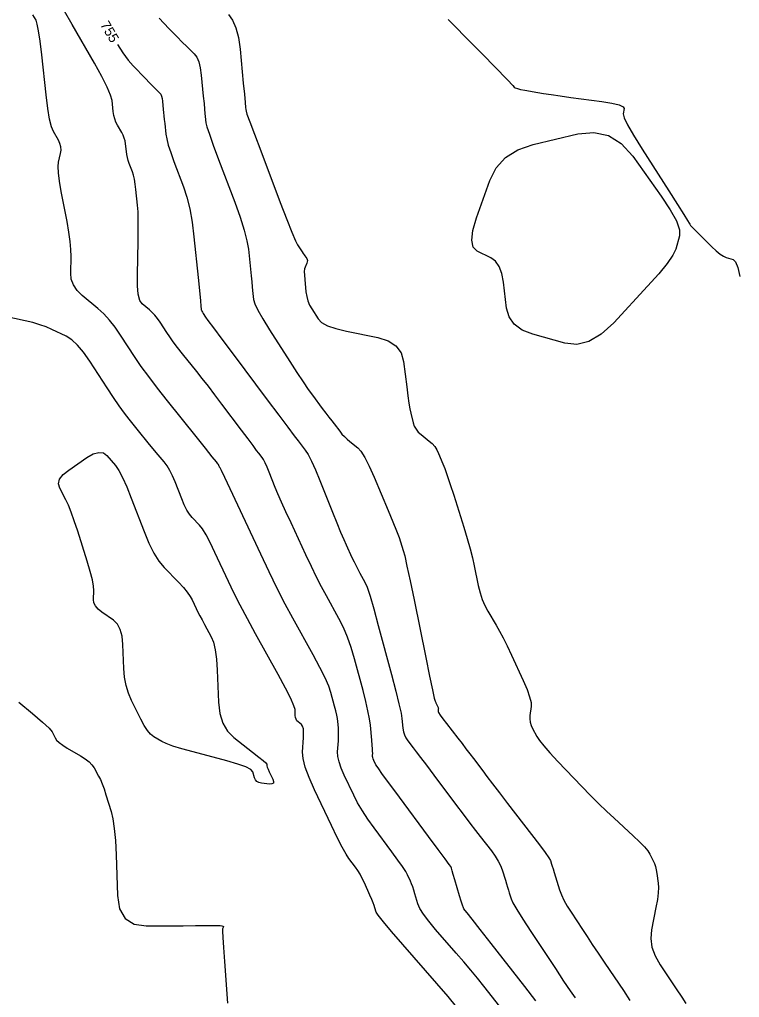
# Model space of a CAD drawing. Extents: x 2082232 to 2083549, y 592624 to 593832.
# Drawn here: x 2082855.5 to 2082906.4, y 592813 to 592882.1 of the extents above; entities that cross this region are included whole.
import ezdxf

# ---------------------------------------------------------------- set-up
doc = ezdxf.new("R2010")
doc.units = 0
doc.layers.add('DT_X_Contour_Major', color=7, linetype='Continuous')
doc.layers.add('DT_X_Contour_Minor', color=7, linetype='Continuous')

msp = doc.modelspace()

# ---------------------------------------------------------------- linework, layer by layer
at = {"layer": 'DT_X_Contour_Major'}
msp.add_lwpolyline([(2082862.437, 592880.32), (2082862.826, 592879.726), (2082863.203, 592879.215), (2082863.545, 592878.821), (2082864.412, 592877.926), (2082864.706, 592877.623), (2082864.939, 592877.384), (2082865.11, 592877.21), (2082865.219, 592877.101), (2082865.427, 592876.896), (2082865.498, 592876.802), (2082865.554, 592876.673), (2082865.596, 592876.511), (2082865.624, 592876.314), (2082865.679, 592875.742), (2082865.7, 592875.519), (2082865.724, 592875.278), (2082865.75, 592875.02), (2082865.779, 592874.744), (2082865.859, 592873.984), (2082865.917, 592873.65), (2082866.032, 592873.218), (2082866.203, 592872.688), (2082866.431, 592872.061), (2082867.114, 592870.256), (2082867.352, 592869.529), (2082867.552, 592868.702), (2082867.716, 592867.774), (2082867.843, 592866.746), (2082868.133, 592863.869), (2082868.297, 592862.237), (2082868.339, 592861.815), (2082868.355, 592861.656), (2082868.363, 592861.582), (2082868.373, 592861.545), (2082868.399, 592861.49), (2082868.44, 592861.417), (2082868.497, 592861.327), (2082868.667, 592861.061), (2082868.837, 592860.822), (2082869.217, 592860.307), (2082869.808, 592859.514), (2082870.609, 592858.444), (2082873.028, 592855.222), (2082873.845, 592854.135), (2082874.481, 592853.289), (2082874.937, 592852.684), (2082875.213, 592852.32), (2082875.708, 592851.672), (2082875.913, 592851.355), (2082876.153, 592850.891), (2082876.431, 592850.278), (2082876.745, 592849.519), (2082877.631, 592847.296), (2082877.942, 592846.525), (2082878.207, 592845.881), (2082878.428, 592845.362), (2082878.604, 592844.97), (2082879.013, 592844.092), (2082879.163, 592843.775), (2082879.308, 592843.482), (2082879.446, 592843.213), (2082879.578, 592842.967), (2082879.921, 592842.345), (2082880.077, 592841.978), (2082880.288, 592841.345), (2082880.554, 592840.445), (2082880.875, 592839.279), (2082881.803, 592835.814), (2082882.11, 592834.645), (2082882.336, 592833.737), (2082882.482, 592833.091), (2082882.546, 592832.705), (2082882.609, 592832.024), (2082882.648, 592831.777), (2082882.719, 592831.546), (2082882.82, 592831.332), (2082882.953, 592831.134), (2082883.349, 592830.627), (2082883.551, 592830.364), (2082883.86, 592829.958), (2082884.275, 592829.407), (2082884.798, 592828.712), (2082886.333, 592826.665), (2082886.874, 592825.946), (2082887.345, 592825.323), (2082887.746, 592824.797), (2082888.077, 592824.366), (2082888.866, 592823.348), (2082889.136, 592822.979), (2082889.353, 592822.636), (2082889.517, 592822.319), (2082889.628, 592822.027), (2082889.853, 592821.285), (2082889.934, 592821.021), (2082890.006, 592820.785), (2082890.07, 592820.577), (2082890.125, 592820.398), (2082890.263, 592819.957), (2082890.389, 592819.69), (2082890.664, 592819.218), (2082891.088, 592818.542), (2082891.661, 592817.661), (2082893.388, 592815.04), (2082893.974, 592814.155), (2082894.438, 592813.466), (2082894.779, 592812.972)], dxfattribs=at)
at = {"layer": 'DT_X_Contour_Minor'}
for points in [[(2082889.453, 592812.364), (2082888.324, 592813.804), (2082887.885, 592814.355), (2082887.415, 592814.928), (2082886.914, 592815.522), (2082886.383, 592816.138), (2082884.925, 592817.811), (2082884.437, 592818.393), (2082884.066, 592818.887), (2082883.811, 592819.291), (2082883.674, 592819.606), (2082883.463, 592820.327), (2082883.384, 592820.585), (2082883.305, 592820.819), (2082883.227, 592821.028), (2082883.149, 592821.213), (2082882.941, 592821.674), (2082882.814, 592821.905), (2082882.588, 592822.25), (2082882.264, 592822.711), (2082881.841, 592823.287), (2082880.583, 592824.977), (2082880.138, 592825.598), (2082879.749, 592826.192), (2082879.415, 592826.759), (2082879.137, 592827.301), (2082878.468, 592828.709), (2082878.251, 592829.207), (2082878.101, 592829.646), (2082878.018, 592830.026), (2082878.002, 592830.345), (2082878.05, 592831.119), (2082878.064, 592831.394), (2082878.069, 592831.64), (2082878.066, 592831.857), (2082878.054, 592832.045), (2082878.011, 592832.506), (2082877.985, 592832.703), (2082877.938, 592832.948), (2082877.872, 592833.24), (2082877.784, 592833.579), (2082877.525, 592834.547), (2082877.373, 592834.986), (2082877.112, 592835.576), (2082876.742, 592836.316), (2082876.263, 592837.208), (2082874.84, 592839.787), (2082874.297, 592840.795), (2082873.736, 592841.887), (2082873.157, 592843.062), (2082872.56, 592844.321), (2082870.943, 592847.787), (2082870.411, 592848.926), (2082870.028, 592849.743), (2082869.794, 592850.237), (2082869.708, 592850.41), (2082869.678, 592850.44), (2082869.667, 592850.454), (2082869.657, 592850.471), (2082869.646, 592850.491), (2082869.636, 592850.516), (2082869.61, 592850.585), (2082869.6, 592850.61), (2082869.589, 592850.631), (2082869.578, 592850.65), (2082869.566, 592850.666), (2082869.533, 592850.704), (2082869.428, 592850.834), (2082869.136, 592851.198), (2082868.658, 592851.794), (2082867.994, 592852.622), (2082865.974, 592855.143), (2082865.263, 592856.044), (2082864.645, 592856.857), (2082864.121, 592857.581), (2082863.689, 592858.218), (2082862.663, 592859.797), (2082862.275, 592860.359), (2082861.878, 592860.859), (2082861.473, 592861.297), (2082861.06, 592861.673), (2082859.948, 592862.595), (2082859.585, 592862.953), (2082859.328, 592863.335), (2082859.178, 592863.742), (2082859.135, 592864.172), (2082859.162, 592865.352), (2082859.152, 592865.839), (2082859.101, 592866.413), (2082859.009, 592867.075), (2082858.876, 592867.825), (2082858.468, 592869.941), (2082858.342, 592870.665), (2082858.267, 592871.25), (2082858.244, 592871.695), (2082858.274, 592872), (2082858.423, 592872.63), (2082858.455, 592872.865), (2082858.439, 592873.098), (2082858.376, 592873.329), (2082858.265, 592873.559), (2082857.907, 592874.169), (2082857.774, 592874.503), (2082857.646, 592875.045), (2082857.522, 592875.798), (2082857.402, 592876.759), (2082857.089, 592879.603), (2082856.975, 592880.555), (2082856.869, 592881.277), (2082856.772, 592881.769), (2082856.682, 592882.032), (2082856.454, 592882.427)], [(2082892.017, 592812.751), (2082891.234, 592813.783), (2082888.859, 592816.811), (2082888.076, 592817.809), (2082887.507, 592818.533), (2082887.154, 592818.981), (2082887.015, 592819.155), (2082886.93, 592819.252), (2082886.887, 592819.337), (2082886.821, 592819.519), (2082886.731, 592819.798), (2082886.618, 592820.175), (2082886.286, 592821.309), (2082886.176, 592821.684), (2082886.095, 592821.957), (2082886.042, 592822.129), (2082886.019, 592822.199), (2082885.996, 592822.251), (2082885.891, 592822.398), (2082885.596, 592822.8), (2082885.109, 592823.457), (2082884.43, 592824.368), (2082882.366, 592827.139), (2082881.682, 592828.062), (2082881.178, 592828.754), (2082880.854, 592829.215), (2082880.71, 592829.445), (2082880.566, 592829.748), (2082880.519, 592829.856), (2082880.487, 592829.95), (2082880.469, 592830.032), (2082880.465, 592830.101), (2082880.476, 592830.268), (2082880.475, 592830.372), (2082880.463, 592830.559), (2082880.442, 592830.83), (2082880.41, 592831.185), (2082880.312, 592832.242), (2082880.252, 592832.692), (2082880.146, 592833.252), (2082879.993, 592833.92), (2082879.794, 592834.697), (2082879.2, 592836.913), (2082878.964, 592837.716), (2082878.7, 592838.46), (2082878.41, 592839.147), (2082878.092, 592839.776), (2082877.209, 592841.377), (2082876.869, 592842.008), (2082876.514, 592842.701), (2082876.143, 592843.455), (2082875.756, 592844.27), (2082874.704, 592846.528), (2082874.338, 592847.319), (2082874.031, 592847.999), (2082873.782, 592848.569), (2082873.592, 592849.028), (2082873.163, 592850.105), (2082873.01, 592850.473), (2082872.876, 592850.769), (2082872.759, 592850.994), (2082872.661, 592851.148), (2082872.421, 592851.462), (2082872.277, 592851.651), (2082872.027, 592851.983), (2082871.67, 592852.457), (2082871.206, 592853.075), (2082869.827, 592854.913), (2082869.327, 592855.574), (2082868.863, 592856.181), (2082868.434, 592856.733), (2082868.04, 592857.229), (2082867.038, 592858.48), (2082866.686, 592858.925), (2082866.384, 592859.321), (2082866.132, 592859.669), (2082865.929, 592859.968), (2082865.453, 592860.701), (2082865.272, 592860.961), (2082865.088, 592861.193), (2082864.9, 592861.396), (2082864.709, 592861.571), (2082864.193, 592861.999), (2082864.026, 592862.249), (2082863.913, 592862.677), (2082863.853, 592863.284), (2082863.846, 592864.069), (2082863.9, 592866.402), (2082863.913, 592867.219), (2082863.91, 592867.92), (2082863.891, 592868.506), (2082863.858, 592868.975), (2082863.747, 592870.072), (2082863.701, 592870.46), (2082863.644, 592870.799), (2082863.576, 592871.09), (2082863.498, 592871.334), (2082863.277, 592871.919), (2082863.202, 592872.136), (2082863.142, 592872.35), (2082863.097, 592872.559), (2082863.068, 592872.764), (2082863.011, 592873.306), (2082862.978, 592873.509), (2082862.922, 592873.709), (2082862.842, 592873.907), (2082862.739, 592874.104), (2082862.432, 592874.625), (2082862.328, 592874.832), (2082862.244, 592875.063), (2082862.181, 592875.317), (2082862.139, 592875.595), (2082862.053, 592876.368), (2082861.951, 592876.749), (2082861.71, 592877.315), (2082861.328, 592878.065), (2082860.806, 592878.998), (2082859.228, 592881.733), (2082858.692, 592882.667)], [(2082870.28, 592882.433), (2082870.577, 592882.039), (2082870.814, 592881.5), (2082870.99, 592880.818), (2082871.106, 592879.993), (2082871.334, 592877.599), (2082871.409, 592876.808), (2082871.465, 592876.232), (2082871.499, 592875.869), (2082871.514, 592875.72), (2082871.526, 592875.609), (2082871.594, 592875.402), (2082871.79, 592874.865), (2082872.114, 592873.998), (2082872.566, 592872.8), (2082873.942, 592869.166), (2082874.405, 592867.957), (2082874.762, 592867.054), (2082875.013, 592866.458), (2082875.158, 592866.169), (2082875.404, 592865.806), (2082875.49, 592865.679), (2082875.566, 592865.568), (2082875.631, 592865.473), (2082875.685, 592865.396), (2082875.815, 592865.212), (2082875.851, 592865.138), (2082875.864, 592865.057), (2082875.854, 592864.968), (2082875.819, 592864.87), (2082875.695, 592864.6), (2082875.659, 592864.469), (2082875.643, 592864.28), (2082875.647, 592864.034), (2082875.671, 592863.729), (2082875.761, 592862.839), (2082875.812, 592862.514), (2082875.896, 592862.206), (2082876.015, 592861.916), (2082876.167, 592861.643), (2082876.619, 592860.939), (2082876.871, 592860.687), (2082877.289, 592860.459), (2082877.872, 592860.255), (2082878.62, 592860.075), (2082880.836, 592859.627), (2082881.574, 592859.396), (2082882.124, 592859.037), (2082882.488, 592858.55), (2082882.664, 592857.937), (2082882.884, 592856.13), (2082882.964, 592855.506), (2082883.039, 592854.989), (2082883.108, 592854.578), (2082883.173, 592854.274), (2082883.338, 592853.606), (2082883.419, 592853.365), (2082883.54, 592853.145), (2082883.699, 592852.944), (2082883.897, 592852.763), (2082884.477, 592852.308), (2082884.682, 592852.124), (2082884.86, 592851.916), (2082885.013, 592851.684), (2082885.139, 592851.426), (2082885.441, 592850.707), (2082885.574, 592850.365), (2082885.745, 592849.879), (2082885.954, 592849.25), (2082886.201, 592848.477), (2082886.913, 592846.223), (2082887.16, 592845.418), (2082887.366, 592844.694), (2082887.533, 592844.05), (2082887.659, 592843.487), (2082887.943, 592842.094), (2082888.064, 592841.59), (2082888.215, 592841.123), (2082888.396, 592840.692), (2082888.607, 592840.299), (2082889.21, 592839.297), (2082889.447, 592838.884), (2082889.705, 592838.395), (2082889.985, 592837.831), (2082890.286, 592837.191), (2082891.117, 592835.384), (2082891.386, 592834.762), (2082891.569, 592834.248), (2082891.667, 592833.845), (2082891.679, 592833.55), (2082891.596, 592832.911), (2082891.583, 592832.675), (2082891.607, 592832.445), (2082891.668, 592832.221), (2082891.766, 592832.003), (2082892.077, 592831.43), (2082892.258, 592831.159), (2082892.568, 592830.777), (2082893.007, 592830.283), (2082893.574, 592829.677), (2082895.26, 592827.913), (2082895.876, 592827.277), (2082896.46, 592826.689), (2082897.013, 592826.152), (2082897.533, 592825.663), (2082898.879, 592824.427), (2082899.332, 592823.998), (2082899.681, 592823.64), (2082899.927, 592823.352), (2082900.069, 592823.134), (2082900.311, 592822.647), (2082900.395, 592822.454), (2082900.466, 592822.243), (2082900.523, 592822.013), (2082900.566, 592821.763), (2082900.665, 592821.072), (2082900.682, 592820.771), (2082900.66, 592820.385), (2082900.599, 592819.915), (2082900.499, 592819.36), (2082900.178, 592817.768), (2082900.127, 592817.167), (2082900.212, 592816.555), (2082900.435, 592815.934), (2082900.795, 592815.303), (2082901.937, 592813.608), (2082902.319, 592813.031), (2082902.607, 592812.574)], [(2082865.38, 592882.172), (2082866.073, 592881.458), (2082866.627, 592880.891), (2082867.04, 592880.47), (2082867.312, 592880.197), (2082867.853, 592879.664), (2082868.037, 592879.42), (2082868.184, 592879.087), (2082868.293, 592878.665), (2082868.365, 592878.153), (2082868.506, 592876.671), (2082868.555, 592876.164), (2082868.594, 592875.755), (2082868.625, 592875.444), (2082868.647, 592875.232), (2082868.692, 592874.796), (2082868.761, 592874.512), (2082868.932, 592873.985), (2082869.207, 592873.215), (2082869.585, 592872.202), (2082870.729, 592869.179), (2082871.112, 592868.121), (2082871.4, 592867.216), (2082871.594, 592866.462), (2082871.693, 592865.861), (2082871.834, 592864.461), (2082871.884, 592863.972), (2082871.925, 592863.556), (2082871.96, 592863.212), (2082871.988, 592862.942), (2082872.051, 592862.317), (2082872.139, 592862.007), (2082872.356, 592861.546), (2082872.702, 592860.933), (2082873.177, 592860.168), (2082874.615, 592857.927), (2082875.119, 592857.148), (2082875.555, 592856.491), (2082875.921, 592855.958), (2082876.218, 592855.547), (2082876.918, 592854.614), (2082877.166, 592854.284), (2082877.387, 592853.991), (2082877.579, 592853.737), (2082877.744, 592853.521), (2082878.145, 592852.996), (2082878.303, 592852.804), (2082878.475, 592852.619), (2082878.662, 592852.443), (2082878.863, 592852.275), (2082879.419, 592851.838), (2082879.648, 592851.585), (2082879.918, 592851.151), (2082880.227, 592850.539), (2082880.578, 592849.746), (2082881.566, 592847.394), (2082881.899, 592846.594), (2082882.158, 592845.958), (2082882.341, 592845.486), (2082882.45, 592845.179), (2082882.639, 592844.578), (2082882.74, 592844.19), (2082882.901, 592843.479), (2082883.121, 592842.443), (2082883.401, 592841.083), (2082884.228, 592837.025), (2082884.501, 592835.69), (2082884.701, 592834.728), (2082884.828, 592834.138), (2082884.883, 592833.923), (2082884.93, 592833.844), (2082884.948, 592833.812), (2082884.969, 592833.774), (2082884.99, 592833.729), (2082885.014, 592833.679), (2082885.079, 592833.538), (2082885.1, 592833.486), (2082885.113, 592833.435), (2082885.118, 592833.385), (2082885.115, 592833.337), (2082885.099, 592833.21), (2082885.131, 592833.121), (2082885.241, 592832.946), (2082885.427, 592832.687), (2082885.69, 592832.343), (2082886.495, 592831.313), (2082886.79, 592830.933), (2082887.071, 592830.569), (2082887.339, 592830.218), (2082887.592, 592829.881), (2082888.251, 592829.003), (2082888.547, 592828.612), (2082888.94, 592828.099), (2082889.429, 592827.464), (2082890.016, 592826.706), (2082891.71, 592824.52), (2082892.27, 592823.791), (2082892.678, 592823.241), (2082892.936, 592822.87), (2082893.042, 592822.679), (2082893.124, 592822.409), (2082893.164, 592822.278), (2082893.223, 592822.087), (2082893.301, 592821.835), (2082893.399, 592821.524), (2082893.683, 592820.614), (2082893.814, 592820.259), (2082893.993, 592819.874), (2082894.221, 592819.461), (2082894.498, 592819.019), (2082895.3, 592817.801), (2082895.625, 592817.31), (2082895.997, 592816.751), (2082896.417, 592816.125), (2082896.884, 592815.43), (2082898.193, 592813.488), (2082898.642, 592812.795)], [(2082885.808, 592882.085), (2082886.405, 592881.49), (2082886.973, 592880.922), (2082887.511, 592880.379), (2082888.019, 592879.862), (2082889.336, 592878.517), (2082889.772, 592878.071), (2082890.093, 592877.739), (2082890.299, 592877.523), (2082890.391, 592877.421), (2082890.481, 592877.304), (2082890.554, 592877.258), (2082890.704, 592877.208), (2082890.932, 592877.153), (2082891.238, 592877.094), (2082892.157, 592876.929), (2082892.561, 592876.862), (2082893.084, 592876.782), (2082893.726, 592876.691), (2082894.487, 592876.587), (2082896.676, 592876.294), (2082897.39, 592876.18), (2082897.892, 592876.058), (2082898.182, 592875.928), (2082898.259, 592875.791), (2082898.181, 592875.413), (2082898.243, 592875.152), (2082898.488, 592874.65), (2082898.916, 592873.908), (2082899.526, 592872.926), (2082901.398, 592869.987), (2082902.014, 592869.018), (2082902.46, 592868.316), (2082902.734, 592867.881), (2082902.836, 592867.712), (2082902.882, 592867.619), (2082902.938, 592867.547), (2082903.072, 592867.403), (2082903.283, 592867.186), (2082903.572, 592866.897), (2082904.448, 592866.028), (2082904.757, 592865.737), (2082905.031, 592865.513), (2082905.267, 592865.358), (2082905.467, 592865.27), (2082905.952, 592865.128), (2082906.126, 592864.96), (2082906.283, 592864.563), (2082906.424, 592863.937)], [(2082889.712, 592863.531), (2082889.594, 592864.153), (2082889.405, 592864.648), (2082889.148, 592865.016), (2082888.82, 592865.258), (2082887.854, 592865.734), (2082887.581, 592866.014), (2082887.485, 592866.496), (2082887.566, 592867.182), (2082887.825, 592868.07), (2082888.75, 592870.71), (2082889.202, 592871.612), (2082889.864, 592872.336), (2082890.736, 592872.883), (2082891.817, 592873.252), (2082894.98, 592874.002), (2082896.112, 592874.116), (2082897.135, 592873.894), (2082898.051, 592873.337), (2082898.858, 592872.445), (2082900.867, 592869.618), (2082901.514, 592868.647), (2082901.947, 592867.854), (2082902.166, 592867.238), (2082902.171, 592866.799), (2082901.901, 592865.867), (2082901.7, 592865.44), (2082901.302, 592864.86), (2082900.705, 592864.127), (2082899.91, 592863.24), (2082897.525, 592860.669), (2082896.637, 592859.856), (2082895.762, 592859.343), (2082894.898, 592859.131), (2082894.047, 592859.219), (2082891.794, 592859.856), (2082891.044, 592860.151), (2082890.485, 592860.557), (2082890.115, 592861.075), (2082889.936, 592861.704), (2082889.712, 592863.531)], [(2082886.407, 592812.35), (2082885.804, 592813.057), (2082885.003, 592813.981), (2082882.6, 592816.738), (2082881.807, 592817.657), (2082881.231, 592818.347), (2082880.872, 592818.807), (2082880.73, 592819.037), (2082880.64, 592819.344), (2082880.592, 592819.486), (2082880.516, 592819.68), (2082880.411, 592819.927), (2082880.278, 592820.227), (2082879.887, 592821.097), (2082879.737, 592821.411), (2082879.581, 592821.701), (2082879.42, 592821.966), (2082879.253, 592822.206), (2082878.799, 592822.815), (2082878.594, 592823.133), (2082878.32, 592823.629), (2082877.976, 592824.304), (2082877.564, 592825.157), (2082876.37, 592827.67), (2082875.981, 592828.543), (2082875.71, 592829.277), (2082875.557, 592829.872), (2082875.522, 592830.328), (2082875.586, 592831.36), (2082875.596, 592831.707), (2082875.576, 592831.976), (2082875.528, 592832.165), (2082875.451, 592832.276), (2082875.206, 592832.466), (2082875.125, 592832.548), (2082875.065, 592832.651), (2082875.027, 592832.775), (2082875.01, 592832.92), (2082874.993, 592833.337), (2082874.913, 592833.609), (2082874.685, 592834.112), (2082874.309, 592834.847), (2082873.786, 592835.813), (2082872.193, 592838.7), (2082871.626, 592839.742), (2082871.118, 592840.706), (2082870.671, 592841.59), (2082870.284, 592842.395), (2082869.332, 592844.437), (2082868.995, 592845.132), (2082868.699, 592845.685), (2082868.444, 592846.098), (2082868.23, 592846.369), (2082867.712, 592846.905), (2082867.521, 592847.138), (2082867.334, 592847.434), (2082867.153, 592847.794), (2082866.977, 592848.217), (2082866.514, 592849.431), (2082866.336, 592849.861), (2082866.148, 592850.238), (2082865.951, 592850.564), (2082865.745, 592850.838), (2082865.181, 592851.499), (2082864.957, 592851.765), (2082864.705, 592852.07), (2082864.426, 592852.411), (2082864.121, 592852.79), (2082863.27, 592853.852), (2082862.934, 592854.288), (2082862.563, 592854.801), (2082862.157, 592855.392), (2082861.716, 592856.059), (2082860.493, 592857.941), (2082860.045, 592858.581), (2082859.617, 592859.089), (2082859.208, 592859.467), (2082858.82, 592859.713), (2082857.81, 592860.196), (2082857.408, 592860.369), (2082856.96, 592860.529), (2082856.465, 592860.674), (2082855.923, 592860.806), (2082854.416, 592861.137)], [(2082861.333, 592840.22), (2082861.064, 592840.438), (2082860.876, 592840.661), (2082860.768, 592840.89), (2082860.741, 592841.124), (2082860.776, 592841.757), (2082860.756, 592842.063), (2082860.67, 592842.509), (2082860.517, 592843.094), (2082860.298, 592843.817), (2082859.626, 592845.933), (2082859.386, 592846.666), (2082859.167, 592847.279), (2082858.97, 592847.771), (2082858.795, 592848.144), (2082858.358, 592848.976), (2082858.275, 592849.291), (2082858.353, 592849.61), (2082858.594, 592849.934), (2082858.995, 592850.262), (2082860.282, 592851.142), (2082860.733, 592851.398), (2082861.119, 592851.506), (2082861.44, 592851.465), (2082861.697, 592851.276), (2082862.295, 592850.574), (2082862.534, 592850.233), (2082862.801, 592849.736), (2082863.095, 592849.085), (2082863.418, 592848.278), (2082864.317, 592845.919), (2082864.659, 592845.096), (2082865.011, 592844.397), (2082865.374, 592843.822), (2082865.746, 592843.37), (2082866.751, 592842.329), (2082867.095, 592841.959), (2082867.371, 592841.628), (2082867.58, 592841.337), (2082867.721, 592841.086), (2082868.009, 592840.47), (2082868.125, 592840.227), (2082868.261, 592839.96), (2082868.414, 592839.669), (2082868.585, 592839.354), (2082869.066, 592838.482), (2082869.228, 592838.09), (2082869.354, 592837.566), (2082869.442, 592836.911), (2082869.495, 592836.124), (2082869.585, 592833.851), (2082869.678, 592833.057), (2082869.887, 592832.378), (2082870.213, 592831.815), (2082870.656, 592831.369), (2082871.993, 592830.331), (2082872.431, 592829.987), (2082872.744, 592829.732), (2082872.931, 592829.567), (2082872.992, 592829.491), (2082872.987, 592829.407), (2082872.997, 592829.355), (2082873.031, 592829.261), (2082873.089, 592829.126), (2082873.17, 592828.95), (2082873.42, 592828.423), (2082873.476, 592828.254), (2082873.456, 592828.14), (2082873.359, 592828.082), (2082873.187, 592828.08), (2082872.625, 592828.149), (2082872.436, 592828.191), (2082872.289, 592828.266), (2082872.185, 592828.373), (2082872.123, 592828.514), (2082872.015, 592828.931), (2082871.869, 592829.098), (2082871.511, 592829.284), (2082870.941, 592829.49), (2082870.159, 592829.716), (2082867.792, 592830.345), (2082866.989, 592830.567), (2082866.352, 592830.762), (2082865.883, 592830.931), (2082865.582, 592831.073), (2082865.002, 592831.416), (2082864.781, 592831.59), (2082864.553, 592831.855), (2082864.32, 592832.212), (2082864.079, 592832.66), (2082863.43, 592833.977), (2082863.214, 592834.489), (2082863.052, 592835.037), (2082862.945, 592835.621), (2082862.893, 592836.241), (2082862.825, 592837.942), (2082862.764, 592838.527), (2082862.632, 592839.006), (2082862.43, 592839.38), (2082862.156, 592839.647), (2082861.333, 592840.22)], [(2082855.458, 592833.864), (2082856.433, 592833.064), (2082857.151, 592832.448), (2082857.613, 592832.016), (2082857.818, 592831.768), (2082858.024, 592831.351), (2082858.135, 592831.188), (2082858.317, 592831.012), (2082858.568, 592830.822), (2082858.888, 592830.619), (2082859.835, 592830.06), (2082860.161, 592829.85), (2082860.428, 592829.639), (2082860.637, 592829.426), (2082860.787, 592829.212), (2082861.11, 592828.64), (2082861.233, 592828.397), (2082861.36, 592828.097), (2082861.491, 592827.738), (2082861.626, 592827.323), (2082861.991, 592826.138), (2082862.116, 592825.614), (2082862.215, 592824.93), (2082862.29, 592824.088), (2082862.339, 592823.086), (2082862.438, 592820.202), (2082862.592, 592819.256), (2082862.983, 592818.582), (2082863.61, 592818.181), (2082864.472, 592818.051), (2082867.087, 592818.067), (2082867.963, 592818.073), (2082868.627, 592818.076), (2082869.081, 592818.078), (2082869.323, 592818.077), (2082869.69, 592818.074), (2082869.808, 592818.067), (2082869.886, 592818.049), (2082869.925, 592818.02), (2082869.925, 592817.979), (2082869.872, 592817.856), (2082869.866, 592817.677), (2082869.885, 592817.233), (2082869.93, 592816.524), (2082870.002, 592815.55), (2082870.227, 592812.598)]]:
    msp.add_lwpolyline(points, dxfattribs=at)

# ---------------------------------------------------------------- texts
at = {"layer": 'DT_X_Contour_Major'}
msp.add_text('755', height=0.7, rotation=300.43176, dxfattribs=at).set_placement((2082861.195, 592881.725))

doc.saveas('drawing.dxf')
